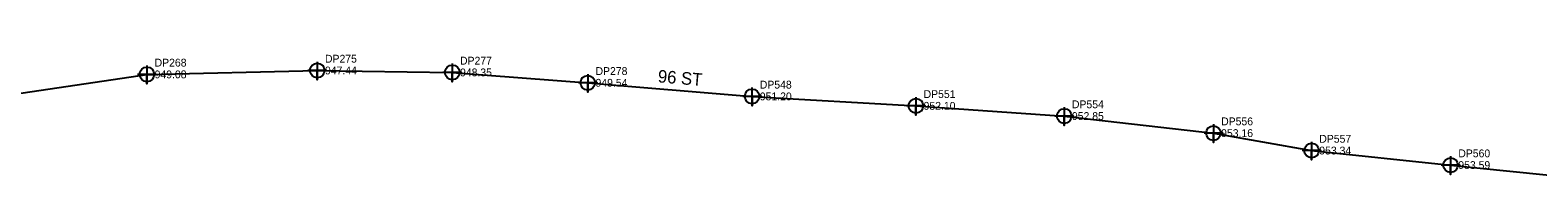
# Model space of a CAD drawing. Extents: x 1182504 to 1186036, y 573002 to 575111.
# Drawn here: x 1185012.2 to 1185495.7, y 573705 to 573755 of the extents above; entities that cross this region are included whole.
import ezdxf

# ---------------------------------------------------------------- set-up
doc = ezdxf.new("R2010")
doc.units = 0
for name, color, linetype in [('Exist Utilities Telephone UG Conduit SUE LOS B', 7, 'Continuous'), ('Exist Utilities Telephone UG Conduit SUE LOS B Cogo Elevation', 7, 'Continuous'), ('Exist Utilities Telephone UG Conduit SUE LOS B Cogo Number', 7, 'Continuous'), ('Exist Utilities Telephone UG Conduit SUE LOS B Cogo Point CELL', 7, 'Continuous'), ('Exist Utilities Telephone UG Conduit SUE LOS B Text', 7, 'Continuous')]:
    doc.layers.add(name, color=color, linetype=linetype)

msp = doc.modelspace()

# ---------------------------------------------------------------- linework, layer by layer
at = {"layer": 'Exist Utilities Telephone UG Conduit SUE LOS B'}
msp.add_lwpolyline([(1184467.17, 573754.95), (1184515.32, 573735.91), (1184558.77, 573733.46), (1184577.16, 573728), (1184617.5, 573724.19), (1184669.81, 573719.04), (1184705.2, 573717.51), (1184761.61, 573719.92), (1184808.75, 573719.14), (1184855.63, 573717.48), (1184899.38, 573717.73), (1184947.65, 573726.76), (1184989.59, 573731.99), (1185049.6, 573740.86), (1185104.23, 573742.11), (1185147.54, 573741.49), (1185190.99, 573738.17), (1185243.67, 573733.83), (1185296.19, 573730.81), (1185343.76, 573727.54), (1185391.61, 573722.1), (1185423.08, 573716.53), (1185467.66, 573711.88), (1185536.39, 573704.97)], dxfattribs=at)
at = {"layer": 'Exist Utilities Telephone UG Conduit SUE LOS B Cogo Point CELL'}
for points in [[(1185104.22, 573744.92), (1185104.25, 573739.11), (1185104.23, 573742.11), (1185107.25, 573742.11), (1185101.25, 573742.11)], [(1185049.59, 573743.68), (1185049.62, 573737.86), (1185049.6, 573740.86), (1185052.62, 573740.86), (1185046.62, 573740.86)], [(1185147.52, 573744.3), (1185147.55, 573738.49), (1185147.54, 573741.49), (1185150.55, 573741.49), (1185144.55, 573741.49)], [(1185190.97, 573740.98), (1185191, 573735.17), (1185190.99, 573738.17), (1185194, 573738.17), (1185188, 573738.17)], [(1185243.65, 573736.65), (1185243.68, 573730.83), (1185243.67, 573733.83), (1185246.68, 573733.83), (1185240.68, 573733.83)], [(1185296.18, 573733.62), (1185296.21, 573727.81), (1185296.19, 573730.81), (1185299.21, 573730.81), (1185293.21, 573730.81)], [(1185343.74, 573730.36), (1185343.77, 573724.54), (1185343.76, 573727.54), (1185346.77, 573727.54), (1185340.77, 573727.54)], [(1185391.6, 573724.92), (1185391.63, 573719.1), (1185391.61, 573722.1), (1185394.63, 573722.1), (1185388.63, 573722.1)], [(1185423.07, 573719.34), (1185423.1, 573713.53), (1185423.08, 573716.53), (1185426.1, 573716.53), (1185420.1, 573716.53)], [(1185467.65, 573714.69), (1185467.68, 573708.88), (1185467.66, 573711.88), (1185470.68, 573711.88), (1185464.68, 573711.88)]]:
    msp.add_lwpolyline(points, dxfattribs=at)
for centre in [(1185049.62, 573740.86), (1185104.25, 573742.11), (1185147.55, 573741.49), (1185191, 573738.17), (1185243.68, 573733.83), (1185296.21, 573730.81), (1185343.77, 573727.54), (1185391.63, 573722.1), (1185423.1, 573716.53), (1185467.68, 573711.88)]:
    msp.add_circle(centre, 2.34, dxfattribs=at)

# ---------------------------------------------------------------- texts
at = {"layer": 'Exist Utilities Telephone UG Conduit SUE LOS B Cogo Elevation'}
for s, p in [('949.08', (1185052.1, 573739.61)), ('947.44', (1185106.73, 573740.86)), ('948.35', (1185150.04, 573740.24)), ('949.54', (1185193.49, 573736.92)), ('951.20', (1185246.17, 573732.58)), ('952.10', (1185298.69, 573729.56)), ('952.85', (1185346.26, 573726.29)), ('953.16', (1185394.11, 573720.85)), ('953.34', (1185425.58, 573715.28)), ('953.59', (1185470.16, 573710.63))]:
    msp.add_text(s, height=2.5, dxfattribs=at).set_placement(p)
at = {"layer": 'Exist Utilities Telephone UG Conduit SUE LOS B Cogo Number'}
for s, p in [('DP268', (1185052.1, 573743.36)), ('DP275', (1185106.73, 573744.61)), ('DP277', (1185150.04, 573743.99)), ('DP278', (1185193.49, 573740.67)), ('DP548', (1185246.17, 573736.33)), ('DP551', (1185298.69, 573733.31)), ('DP554', (1185346.26, 573730.04)), ('DP556', (1185394.11, 573724.6)), ('DP557', (1185425.58, 573719.03)), ('DP560', (1185470.16, 573714.38))]:
    msp.add_text(s, height=2.5, dxfattribs=at).set_placement(p)
at = {"layer": 'Exist Utilities Telephone UG Conduit SUE LOS B Text'}
msp.add_text('96 ST', height=4, rotation=355.2995, dxfattribs=at).set_placement((1185213.35, 573738.33))

doc.saveas('drawing.dxf')
